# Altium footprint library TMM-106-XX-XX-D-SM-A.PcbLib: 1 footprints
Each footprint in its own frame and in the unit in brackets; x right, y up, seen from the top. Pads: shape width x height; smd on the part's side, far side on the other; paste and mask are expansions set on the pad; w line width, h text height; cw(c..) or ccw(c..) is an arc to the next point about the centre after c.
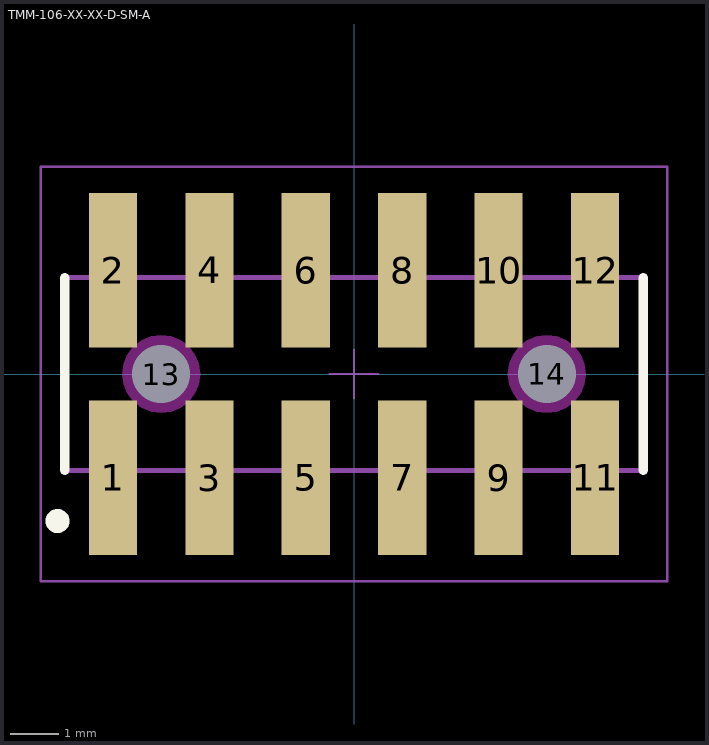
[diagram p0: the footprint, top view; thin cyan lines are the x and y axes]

## TMM-106-XX-XX-D-SM-A [mm] "2.00mm pitch, 12 pin, terminal strip; double row, w/alignment pins, SMT"
height 2.77
pads (14):
  rect 1x3.2 smd mask+0: 1(-5,-2.15) 2(-5,2.15) 3(-3,-2.15) 4(-3,2.15) 5(-1,-2.15) 6(-1,2.15) 7(1,-2.15) 8(1,2.15) 9(3,-2.15) 10(3,2.15) 11(5,-2.15) 12(5,2.15)
  round 1 hole 1.2 unplated mask+0: 13(-4,0) 14(4,0)
Top Overlay:
  circle w0.25: c-6.15,-3.05 r0.125
  lines w0.2: -6,-2 -6,2 ; 6,-2 6,2
Keep-Out Layer:
  pour cut-out: -3.193,0 -3.221,0.209 -3.301,0.403 -3.429,0.571 -3.597,0.699 -3.791,0.779 -4,0.807 -4.209,0.779 -4.403,0.699 -4.571,0.571 -4.699,0.403 -4.779,0.209 -4.807,0 -4.779,-0.209 -4.699,-0.403 -4.571,-0.571 -4.403,-0.699 -4.209,-0.779 -4,-0.807 -3.791,-0.779 -3.597,-0.699 -3.429,-0.571 -3.301,-0.403 -3.221,-0.209
  pour cut-out: 4.807,0 4.779,0.209 4.699,0.403 4.571,0.571 4.403,0.699 4.209,0.779 4,0.807 3.791,0.779 3.597,0.699 3.429,0.571 3.301,0.403 3.221,0.209 3.193,0 3.221,-0.209 3.301,-0.403 3.429,-0.571 3.597,-0.699 3.791,-0.779 4,-0.807 4.209,-0.779 4.403,-0.699 4.571,-0.571 4.699,-0.403 4.779,-0.209
Mechanical 12:
  lines w0.001: -6,-2 6,-2 6,2 -6,2 -6,-2
Mechanical 13:
  lines w0.1: -6,-2 6,-2 6,2 -6,2 -6,-2
  text ".Designator" at 0,-0.127 h1.52
Mechanical 15:
  lines w0.05: -0.5,0 0.5,0 ; 0,-0.5 0,0.5 ; -6.5,-4.3 6.5,-4.3 6.5,4.3 -6.5,4.3 -6.5,-4.3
